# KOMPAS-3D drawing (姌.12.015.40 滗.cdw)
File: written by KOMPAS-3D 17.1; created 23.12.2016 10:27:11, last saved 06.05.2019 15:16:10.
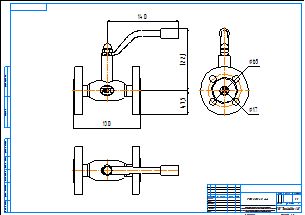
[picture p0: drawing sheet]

Sheet 1: A2, landscape

Title block, sheet 1: name: КШ.12.015.40 фф; material: Внимание! Данный продукт является объектом авторского права ООО «Торговый Дом АДЛ». / Запрещается изменение, копирование, распространение / (в том числе путем копирования на другие сайты и ресурсы в Интернете) / или любое иное использование информации и объектов без предварительного / согласия правообладателя (ООО «Торговый Дом АДЛ»).; sheets: 1; organisation: ООО "Торговый дом АДЛ"; sheet format: A2; stored path: C:\Users\tra\Desktop\2д чертежи\Шаровые краны БИВАЛ\КШ_Бивал_серия_11_12\KOMPAS_2D\КШ.12.015.40 фф.cdw

Views: Спереди 4, Проекционный вид 5, Проекционный вид 6
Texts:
  Klimkovich
  ADL
Dimensions and other numbers on the sheet: 130; 140; 122,1; 47,5; 65; 17; 1:1; 1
